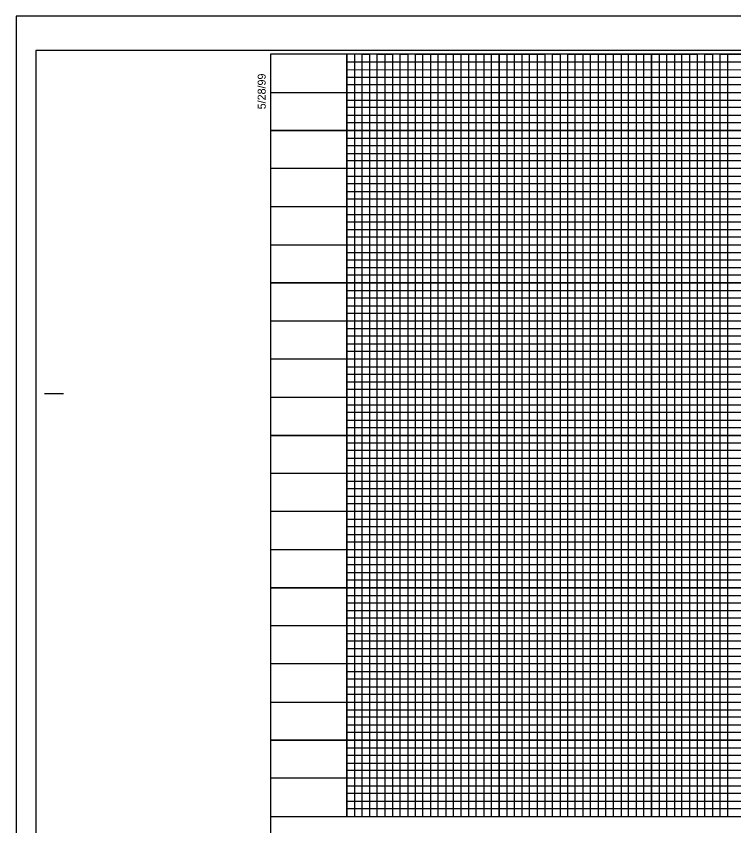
# Model space of a CAD drawing. Extents: x 553912 to 567693, y 512355 to 537539.
# Drawn here: x 565534 to 566005, y 513959 to 514490 of the extents above; entities that cross this region are included whole.
import ezdxf

# ---------------------------------------------------------------- set-up
doc = ezdxf.new("R2010")
doc.units = 0
for name, color, linetype in [('Sheet Cutting Line CELL', 7, 'Continuous'), ('Sheet DOT Grid CELL', 7, 'Continuous'), ('Sheet Layout Profile Border Port 1', 7, 'Continuous'), ('Sheet Plot Border Inside CELL', 7, 'Continuous'), ('Sheet Plot Border Outside CELL', 7, 'Continuous'), ('Sheet Profile CELL', 7, 'Continuous'), ('Sheet Profile Grid Major CELL', 7, 'Continuous'), ('Sheet Profile Grid Middle CELL', 7, 'Continuous'), ('Sheet Profile Grid Minor CELL', 7, 'Continuous')]:
    doc.layers.add(name, color=color, linetype=linetype)

msp = doc.modelspace()

# ---------------------------------------------------------------- linework, layer by layer
at = {"layer": 'Sheet Cutting Line CELL'}
for p, q in [((567218.35, 514489.72), (565534.35, 514489.72)), ((565534.35, 514489.72), (565534.35, 513389.72))]:
    msp.add_line(p, q, dxfattribs=at)
at = {"layer": 'Sheet DOT Grid CELL'}
for p, q in [((565751.35, 513964.72), (565751.35, 514464.72)), ((565801.35, 513964.72), (565801.35, 514464.72)), ((565851.35, 513964.72), (565851.35, 514464.72)), ((565901.35, 513964.72), (565901.35, 514464.72)), ((565951.35, 513964.72), (565951.35, 514464.72)), ((566001.35, 513964.72), (566001.35, 514464.72)), ((567001.3, 514414.72), (565701.35, 514414.72)), ((567001.3, 514364.72), (565701.35, 514364.72)), ((567001.35, 514314.72), (565701.35, 514314.72)), ((567201.35, 514264.72), (565701.35, 514264.72)), ((567201.35, 514214.72), (565701.35, 514214.72)), ((567201.35, 514164.72), (565701.35, 514164.72)), ((567201.35, 514114.72), (565701.35, 514114.72)), ((567201.35, 514064.72), (565701.35, 514064.72)), ((567201.35, 514014.72), (565701.35, 514014.72))]:
    msp.add_line(p, q, dxfattribs=at)
at = {"layer": 'Sheet Layout Profile Border Port 1'}
msp.add_lwpolyline([(565751.35, 514303.67), (565751.35, 513964.72), (567151.35, 513964.72), (567151.35, 514303.67)], dxfattribs=at)
at = {"layer": 'Sheet Plot Border Inside CELL'}
msp.add_lwpolyline([(565547.35, 513412.17), (567213.85, 513412.17), (567213.85, 514467.27), (565547.35, 514467.27)], close=True, dxfattribs=at)
at = {"layer": 'Sheet Plot Border Outside CELL'}
msp.add_lwpolyline([(565534.35, 513389.72), (567218.35, 513389.72), (567218.35, 514489.72), (565534.35, 514489.72)], close=True, dxfattribs=at)
at = {"layer": 'Sheet Profile CELL'}
for p, q in [((565552.85, 514242.22), (565565.35, 514242.22)), ((565701.35, 513964.72), (567201.35, 513964.72))]:
    msp.add_line(p, q, dxfattribs=at)
msp.add_lwpolyline([(567201.35, 514464.72), (565701.35, 514464.72), (565701.35, 513414.72), (567201.35, 513414.72)], close=True, dxfattribs=at)
at = {"layer": 'Sheet Profile Grid Major CELL'}
for points in [[(565751.35, 514464.72), (565751.35, 513964.72), (565801.35, 513964.72), (565801.35, 514464.72), (565851.35, 514464.72), (565851.35, 513964.72), (565901.35, 513964.72), (565901.35, 514464.72), (565951.35, 514464.72), (565951.35, 513964.72), (566001.35, 513964.72), (566001.35, 514464.72), (566051.35, 514464.72)], [(565701.35, 514414.72), (567001.35, 514414.72)], [(567001.35, 514364.72), (565701.35, 514364.72), (565701.35, 514314.72), (567001.35, 514314.72)], [(567201.35, 514264.72), (565701.35, 514264.72), (565701.35, 514214.72), (567201.35, 514214.72)], [(567201.35, 514164.72), (565701.35, 514164.72), (565701.35, 514114.72), (567201.35, 514114.72)], [(567201.35, 514064.72), (565701.35, 514064.72), (565701.35, 514064.72), (565701.35, 514014.72), (567201.35, 514014.72)]]:
    msp.add_lwpolyline(points, dxfattribs=at)
at = {"layer": 'Sheet Profile Grid Middle CELL'}
msp.add_line((565701.35, 514439.72), (567001.3, 514439.72), dxfattribs=at)
for points in [[(565776.35, 514464.72), (565776.35, 513964.72), (565826.35, 513964.72), (565826.35, 514464.72), (565876.35, 514464.72), (565876.35, 513964.72), (565926.35, 513964.72), (565926.35, 514464.72), (565976.35, 514464.72), (565976.35, 513964.72), (566026.35, 513964.72)], [(567001.35, 514389.72), (565701.35, 514389.72), (565701.35, 514339.72), (567001.35, 514339.72)], [(567201.35, 514289.72), (565701.35, 514289.72), (565701.35, 514239.72), (567026.35, 514239.72)], [(567201.35, 514189.72), (565701.35, 514189.72), (565701.35, 514139.72), (567201.35, 514139.72)], [(567201.35, 514089.72), (565701.35, 514089.72), (565701.35, 514039.72), (567201.35, 514039.72)], [(567201.35, 513989.72), (565701.35, 513989.72)]]:
    msp.add_lwpolyline(points, dxfattribs=at)
at = {"layer": 'Sheet Profile Grid Minor CELL'}
for p, q in [((565751.35, 514459.72), (567001.35, 514459.72)), ((565751.35, 514454.72), (565751.35, 514454.72)), ((567001.35, 514454.72), (565751.35, 514454.37)), ((565751.35, 514449.72), (567001.35, 514449.72)), ((567001.3, 514329.72), (565751.35, 514329.72)), ((567001.35, 514324.72), (565751.35, 514324.72)), ((567001.35, 514319.72), (565751.35, 514319.72)), ((565751.35, 514309.72), (567001.35, 514309.72)), ((567001.35, 514304.72), (565751.35, 514304.72)), ((565751.35, 514299.72), (567151.35, 514299.72)), ((567151.35, 514279.72), (565751.35, 514279.72)), ((565751.35, 514274.72), (567151.35, 514274.72)), ((567151.35, 514254.72), (565751.35, 514254.72)), ((565751.35, 514249.72), (567151.35, 514249.72)), ((567151.35, 514229.72), (565751.35, 514229.72)), ((565751.35, 514224.72), (567151.35, 514224.72)), ((567151.35, 514219.72), (565751.35, 514219.72)), ((565751.35, 514209.72), (567151.35, 514209.72)), ((567151.35, 514204.72), (565751.35, 514204.72)), ((565751.35, 514199.72), (567151.35, 514199.72)), ((567151.35, 514194.72), (565751.35, 514194.72)), ((565751.35, 514184.72), (567151.35, 514184.72)), ((567151.35, 514179.72), (565751.35, 514179.72)), ((565751.35, 514174.72), (567151.35, 514174.72)), ((567151.35, 514169.72), (565751.35, 514169.72)), ((565751.35, 514159.72), (567151.35, 514159.72)), ((567151.35, 514154.72), (565751.35, 514154.72)), ((565751.35, 514149.72), (567151.35, 514149.72)), ((567151.35, 514144.72), (565751.35, 514144.72)), ((565751.35, 514134.72), (567151.35, 514134.72)), ((567151.35, 514129.72), (565751.35, 514129.72)), ((565751.35, 514124.72), (567151.35, 514124.72)), ((567151.35, 514119.72), (565751.35, 514119.72)), ((565751.35, 514109.72), (567151.35, 514109.72)), ((567151.35, 514104.72), (565751.35, 514104.72)), ((565751.35, 514099.72), (567151.35, 514099.72)), ((567151.35, 514094.72), (565751.35, 514094.72)), ((565751.35, 514084.72), (567151.35, 514084.72)), ((567151.35, 514079.72), (565751.35, 514079.72)), ((567151.35, 514074.72), (565751.35, 514074.72)), ((567151.35, 514069.72), (565751.35, 514069.72)), ((565751.35, 514059.72), (567151.35, 514059.72)), ((567151.35, 514054.72), (565751.35, 514054.72)), ((565751.35, 514049.72), (567151.35, 514049.72)), ((567151.35, 514044.72), (565751.35, 514044.72)), ((565751.35, 514034.72), (567151.35, 514034.72)), ((567151.35, 514029.72), (565751.35, 514029.72)), ((565751.35, 514024.72), (567151.35, 514024.72)), ((567151.35, 514019.72), (565751.35, 514019.72)), ((565751.35, 514009.72), (567151.35, 514009.72)), ((567151.35, 514004.72), (565751.35, 514004.72)), ((565751.35, 513999.72), (567151.35, 513999.72)), ((567151.35, 513994.72), (565751.35, 513994.72)), ((565751.35, 513984.72), (567151.35, 513984.72)), ((567151.35, 513979.72), (565751.35, 513979.72)), ((565751.35, 513974.72), (567151.35, 513974.72))]:
    msp.add_line(p, q, dxfattribs=at)
for points in [[(565756.35, 514464.72), (565756.35, 513964.72), (565761.35, 513964.72), (565761.35, 514464.72), (565766.35, 514464.72), (565766.35, 513964.72), (565771.35, 513964.72), (565771.35, 514464.72), (565781.35, 514464.72), (565781.35, 513964.72), (565786.35, 513964.72), (565786.35, 514464.72), (565791.35, 514464.72), (565791.35, 513964.72), (565796.35, 513964.72), (565806.35, 513964.72), (565811.35, 513964.72), (565811.35, 514464.72), (565816.35, 514464.72), (565816.35, 513964.72), (565821.35, 513964.72), (565821.35, 514464.72), (565831.35, 514464.72), (565831.35, 513964.72), (565836.35, 513964.72), (565836.35, 514464.72), (565841.35, 514464.72), (565841.35, 513964.72), (565846.35, 513964.72), (565846.35, 514464.72), (565856.35, 514464.72), (565856.35, 513964.72), (565861.35, 513964.72), (565861.35, 514464.72), (565866.35, 514464.72), (565866.35, 513964.72), (565871.35, 513964.72), (565871.35, 514464.72), (565881.35, 514464.72), (565881.35, 513964.72), (565886.35, 513964.72), (565886.35, 514464.72), (565891.35, 514464.72), (565891.35, 513964.72), (565896.35, 513964.72), (565896.35, 514464.72), (565906.35, 514464.72), (565906.35, 513964.72), (565911.35, 513964.72), (565911.35, 514464.72), (565916.35, 514464.72), (565916.35, 513964.72), (565921.35, 513964.72), (565921.35, 514464.72), (565931.35, 514464.72), (565931.35, 513964.72), (565936.35, 513964.72), (565936.35, 514464.72), (565941.35, 514464.72), (565941.35, 513964.72), (565946.35, 513964.72), (565946.35, 514464.72), (565956.35, 514464.72), (565956.35, 513964.72), (565961.35, 513964.72), (565961.35, 514464.72), (565966.35, 514464.72), (565966.35, 513964.72)], [(565796.35, 513964.72), (565796.35, 514464.72), (565806.35, 514464.72), (565806.35, 513964.72)], [(565966.35, 513964.72), (565971.35, 513964.72), (565971.35, 514464.72), (565981.35, 514464.72), (565981.35, 513964.72), (565986.35, 513964.72), (565986.35, 514464.72), (565991.35, 514464.72), (565991.35, 513964.72), (565996.35, 513964.72), (565996.35, 514464.72), (566006.35, 514464.72)], [(567001.35, 514444.72), (565751.35, 514444.72), (565751.35, 514434.72), (567001.35, 514434.72)], [(567001.3, 514429.72), (565751.35, 514429.72), (565751.35, 514424.72), (567001.35, 514424.72)], [(567001.35, 514419.72), (565751.35, 514419.72), (565751.35, 514409.72), (567001.35, 514409.72)], [(567001.35, 514404.72), (565751.35, 514404.72), (565751.35, 514399.72), (567001.35, 514399.72)], [(567001.35, 514394.72), (565751.35, 514394.72), (565751.35, 514384.72), (567001.35, 514384.72)], [(567001.35, 514379.72), (565751.35, 514379.72), (565751.35, 514374.72), (567001.35, 514374.72)], [(567001.35, 514369.72), (565751.35, 514369.72), (565751.35, 514359.72), (567001.35, 514359.72)], [(567001.35, 514354.62), (565751.45, 514354.62), (565751.45, 514349.72), (567001.35, 514349.72)], [(567001.35, 514344.72), (565751.35, 514344.72), (565751.35, 514334.72), (567001.35, 514334.72)], [(567151.35, 514294.72), (565751.35, 514294.72), (565751.35, 514284.72), (567151.35, 514284.72)], [(567151.35, 514269.72), (565751.35, 514269.72), (565751.35, 514259.72), (567151.35, 514259.72)], [(567151.35, 514244.72), (565751.35, 514244.72), (565751.35, 514234.72), (567151.35, 514234.72)], [(567151.35, 513969.72), (565751.35, 513969.72)]]:
    msp.add_lwpolyline(points, dxfattribs=at)

# ---------------------------------------------------------------- texts
at = {"layer": 'Sheet Profile CELL'}
msp.add_text('5/28/99', height=5.25, rotation=90, dxfattribs=at).set_placement((565698.12, 514428.63))

doc.saveas('drawing.dxf')
